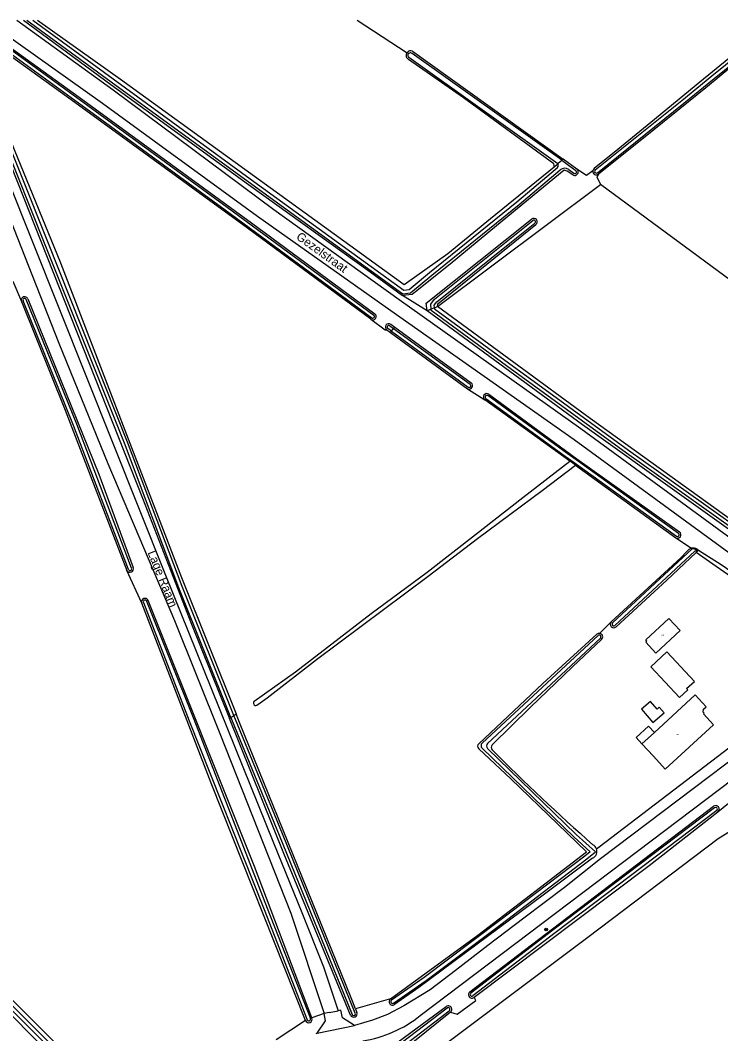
# Model space of a CAD drawing. Extents: x 141000 to 143000, y 400580 to 403500.
# Drawn here: x 142605.5 to 142807.3, y 403208 to 403500 of the extents above; entities that cross this region are included whole.
import ezdxf

# ---------------------------------------------------------------- set-up
doc = ezdxf.new("R2010")
doc.units = 0
for name, color, linetype in [('gg-anno-openbare ruimte label', 7, 'Continuous'), ('gg-bbg-luifel en loopbrug', 7, 'Continuous'), ('gg-bbg-overig bouwwerk', 7, 'Continuous'), ('gg-knt-bronhoudergrens', 7, 'Continuous'), ('gg-knt-onverhard', 7, 'Continuous'), ('gg-knt-verharding', 7, 'Continuous'), ('gg-kntw-bovenkant insteek waterloop', 7, 'Continuous'), ('gg-kntw-waterlijn', 7, 'Continuous'), ('gt-grn-groengrens', 7, 'Continuous'), ('gt-grn-vlakafsluiter', 7, 'Continuous'), ('gt-symb-boom', 7, 'Continuous'), ('gx-grn-maaiveld', 7, 'Continuous'), ('kenmerkpunt-x pandkandidaat', 7, 'Continuous')]:
    doc.layers.add(name, color=color, linetype=linetype)

# ---------------------------------------------------------------- blocks, each defined once
blk = doc.blocks.new('gt0-BOOM')
at = {"layer": 'gt-symb-boom'}
for radius in [0.4, 0.2]:
    blk.add_circle((0, 0), radius, dxfattribs=at)

msp = doc.modelspace()

# ---------------------------------------------------------------- linework, layer by layer
at = {"layer": 'gg-bbg-luifel en loopbrug'}
msp.add_line((142788.18, 403294.8), (142784.59, 403291.5), dxfattribs=at)
msp.add_lwpolyline([(142788.18, 403294.8), (142786.48, 403296.64), (142782.9, 403293.34), (142784.59, 403291.5)], dxfattribs=at)
at = {"layer": 'gg-bbg-overig bouwwerk'}
for points in [[(142797.46, 403307.41), (142799.7, 403309.49), (142791.8, 403318), (142787.17, 403313.7), (142795.37, 403304.87), (142797.76, 403307.09), (142797.46, 403307.41)], [(142789.56, 403302.04), (142788.95, 403301.51), (142787.03, 403303.74), (142784.41, 403301.48), (142787.74, 403297.63), (142790.96, 403300.41), (142789.56, 403302.04)]]:
    msp.add_lwpolyline(points, dxfattribs=at)
at = {"layer": 'gg-knt-bronhoudergrens'}
for p, q in [((142825.88, 403413.4), (142772.65, 403452.66)), ((142640.51, 403332.06), (142636.22, 403341.49)), ((142687.67, 403211.8), (142679.2, 403206.19))]:
    msp.add_line(p, q, dxfattribs=at)
msp.add_lwpolyline([(142724.1, 403202.14), (142744.38, 403217.33), (142769.01, 403235.83), (142806.51, 403264.25), (142811.3, 403267.21), (142815.02, 403266.93), (142818.46, 403266.27), (142827.61, 403256.01), (142851.53, 403228.52), (142860.35, 403218.34), (142869.79, 403206.95)], dxfattribs=at)
at = {"layer": 'gg-knt-onverhard'}
for p, q in [((142725.71, 403417.52), (142772.65, 403452.66)), ((142603.33, 403424.78), (142605.82, 403418.96)), ((142734.29, 403393.84), (142739.3, 403390.63)), ((142794.32, 403350.9), (142798.86, 403347.86)), ((142775.73, 403326.66), (142772.35, 403323.34)), ((142712.14, 403218.02), (142702.06, 403215.16))]:
    msp.add_line(p, q, dxfattribs=at)
msp.add_lwpolyline([(142706.45, 403413.83), (142710.6, 403410.83), (142711.06, 403410.77)], dxfattribs=at)
at = {"layer": 'gg-knt-verharding'}
for p, q in [((142694.45, 403214.07), (142693.01, 403213.78)), ((142694.45, 403214.07), (142697.08, 403214.59)), ((142691, 403208.13), (142701.74, 403210.4))]:
    msp.add_line(p, q, dxfattribs=at)
for points in [[(142580.86, 403500), (142581.54, 403498.3), (142583.38, 403492.84), (142588.51, 403478.21), (142592.66, 403467.56), (142616.56, 403406.94), (142630.76, 403372.28), (142649.91, 403327.04), (142662.96, 403294.46), (142683.41, 403242.72), (142693.01, 403213.78)], [(142585.17, 403500), (142591.93, 403477.83), (142601.39, 403455.15), (142647.31, 403340.12), (142678.4, 403262.94), (142686.61, 403242.88), (142692.87, 403227.3), (142697.08, 403214.59)], [(142595.45, 403500), (142629.17, 403476.1), (142673.83, 403443.54), (142712.26, 403416.36), (142765.07, 403379.18), (142812.16, 403344.83), (142845.71, 403319.06)], [(142604.52, 403500), (142632.22, 403479.92), (142678.54, 403445.48), (142714.62, 403419.55), (142767.02, 403382.42), (142814.6, 403347.5), (142848.6, 403321.46)], [(142720.69, 403213.22), (142849.81, 403310.95), (142851.32, 403311.94)], [(142817.41, 403292.17), (142772.6, 403258.33), (142762.3, 403250.12), (142750.55, 403241.24), (142740.23, 403233.43), (142730.9, 403226.22), (142723.56, 403220.59), (142715.99, 403216.06), (142711.33, 403213.56), (142706.94, 403211.9), (142701.74, 403210.4)], [(142691, 403208.13), (142693.4, 403211.67), (142693.01, 403213.78)], [(142701.74, 403210.4), (142698.3, 403212.61), (142697.85, 403214.74), (142697.08, 403214.59)]]:
    msp.add_lwpolyline(points, dxfattribs=at)
msp.add_arc((142698.62, 403240.77), 35.3, 279.016, 308.6824, dxfattribs=at)
at = {"layer": 'gg-kntw-bovenkant insteek waterloop'}
for p, q in [((142718.48, 403491.13), (142761.89, 403459.95)), ((142765.85, 403457.11), (142761.89, 403459.95)), ((142712.24, 403412.39), (142713.37, 403411.56)), ((142713.37, 403411.56), (142735.38, 403395.51)), ((142711.06, 403410.77), (142712.11, 403410.01)), ((142712.11, 403410.01), (142734.29, 403393.84)), ((142763.85, 403372.96), (142739.3, 403390.63)), ((142765.44, 403371.79), (142794.32, 403350.9)), ((142800.49, 403347.58), (142800.91, 403347.31)), ((142824.75, 403329.45), (142800.19, 403346.65)), ((142735, 403220.05), (142805.23, 403273.51)), ((142702.06, 403215.16), (142702.47, 403214.12))]:
    msp.add_line(p, q, dxfattribs=at)
for points in [[(142589.32, 403500), (142588.32, 403498.23), (142595.87, 403475.4), (142640.71, 403362.28), (142654.81, 403325.96), (142665.77, 403298.81)], [(142591.29, 403500), (142591.97, 403499.88), (142622.44, 403477.83), (142672.13, 403441.68), (142707.63, 403415.45)], [(142606.4, 403500), (142631.57, 403481.47), (142671.28, 403452.65), (142706.32, 403427.52), (142715.57, 403420.68)], [(142610.41, 403500), (142634.4, 403483.03), (142716.07, 403423.83), (142728.67, 403432.77), (142740.99, 403442.9), (142759.27, 403457.81)], [(142706.45, 403413.83), (142670.95, 403440.11), (142621.19, 403476.34), (142591.57, 403497.67), (142591.07, 403497.32), (142597.37, 403478.02), (142617.11, 403430.15), (142651.96, 403339.43), (142667.73, 403300.2)], [(142759.27, 403457.81), (142759.34, 403458.23), (142759.21, 403458.62), (142733.19, 403477.63), (142717.35, 403488.72)], [(142764.66, 403455.5), (142763, 403456.54), (142762.22, 403456.79), (142742.68, 403440.75), (142729.31, 403429.75), (142719.32, 403421.77), (142718.42, 403420.97), (142715.57, 403420.68)], [(142722.71, 403416.24), (142722.41, 403418.46), (142752.79, 403442.7)], [(142725.71, 403417.52), (142725.74, 403418.29), (142754.05, 403441.14)], [(142605.82, 403418.96), (142618.4, 403387.7), (142636.22, 403341.49)], [(142607.68, 403419.72), (142628.11, 403369.24), (142638.04, 403342.31)], [(142893.17, 403355.15), (142861.1, 403330.58), (142853.67, 403324.76), (142852.71, 403324.86), (142818.65, 403349.97), (142769.65, 403385.22), (142725.71, 403417.52)], [(142853.32, 403322.06), (142767.49, 403383.4), (142722.71, 403416.24)], [(142740.48, 403392.24), (142765.8, 403373.67), (142795.43, 403352.56)], [(142672.88, 403303.84), (142684.8, 403312.27), (142706.58, 403329.06), (142722.69, 403341.02), (142736.64, 403351.87), (142750.3, 403362.48), (142763.85, 403372.96)], [(142673.9, 403302.83), (142676.58, 403304.73), (142690.83, 403315.77), (142723.04, 403339.78), (142737.22, 403350.68), (142755.8, 403364.5), (142765.44, 403371.79)], [(142800.91, 403347.31), (142807.38, 403343.19), (142825.51, 403330.74)], [(142775.73, 403326.66), (142795.77, 403345.07), (142797.55, 403346.92)], [(142800.19, 403346.65), (142791.79, 403338.64), (142777.13, 403325.24)], [(142689.53, 403212.53), (142672.99, 403256.21), (142642.37, 403332.79)], [(142687.67, 403211.8), (142660.44, 403280.2), (142640.51, 403332.06)], [(142771.6, 403323.07), (142756.03, 403308.9), (142737.58, 403291.56)], [(142772.96, 403321.61), (142764.55, 403313.73), (142752.47, 403302.06), (142741.43, 403291.2)], [(142700.63, 403213.35), (142681.46, 403259.95), (142665.77, 403298.81)], [(142702.06, 403215.16), (142700.83, 403218.32), (142668.65, 403297.67), (142667.73, 403300.2)], [(142712.14, 403218.02), (142737.33, 403236.4), (142755.32, 403250.18), (142768.64, 403260.4), (142760.31, 403268.39), (142746.84, 403281.38), (142737.56, 403290.08)], [(142640.83, 403175.69), (142632.08, 403184.36), (142617.37, 403198.78), (142602.25, 403214), (142584.13, 403231.28), (142569.16, 403246.61), (142552.14, 403263.78), (142545.24, 403271.12)], [(142547.36, 403273.24), (142563.78, 403256.69), (142581.71, 403239.05), (142615.56, 403205.33), (142633.58, 403187.1), (142640.07, 403180.8), (142642.94, 403177.82)], [(142736.22, 403218.47), (142786.68, 403256.48), (142806.49, 403271.96)], [(142770.32, 403258.54), (142756.54, 403248.17), (142720.32, 403221.27), (142713.31, 403216.4)], [(142706.76, 403199.23), (142707.49, 403200.53), (142728.18, 403215.79)], [(142729.39, 403214.2), (142711.65, 403199.89), (142710.56, 403198.2)]]:
    msp.add_lwpolyline(points, dxfattribs=at)
for centre, radius, start, end in [((142718.01, 403489.88), 1.34, 145.3975, 240.2162), ((142718.01, 403489.88), 1.34, 69.6816, 145.3766), ((142765.25, 403456.3), 1, 233.5938, 53.6059), ((142771.45, 403456.47), 1, 170.6247, 308.752), ((142771.45, 403456.47), 1, 128.8208, 170.5738), ((142753.42, 403441.92), 1, 308.9189, 128.9019), ((142606.75, 403419.34), 1, 22.0612, 202.1162), ((142707.03, 403414.65), 1, 234.5159, 53.6359), ((142711.65, 403411.58), 1, 53.7954, 233.7708), ((142734.78, 403394.71), 1, 240.5064, 53.7852), ((142739.89, 403391.43), 1, 53.901, 233.8715), ((142794.84, 403351.75), 1, 238.0782, 54.4781), ((142799.34, 403345.81), 2.11, 103.1503, 148.2379), ((142799.34, 403345.82), 2.1, 56.8121, 103.1438), ((142637.11, 403341.96), 1, 208.064, 20.8049), ((142641.44, 403332.43), 1, 21.3716, 201.3163), ((142776.45, 403325.97), 1, 136.0569, 312.8487), ((142772.28, 403322.34), 1, 86.2079, 132.896), ((142772.28, 403322.34), 1, 313.023, 86.1965), ((142673.36, 403303.3), 0.723, 131.8106, 319.2005), ((142738.24, 403290.81), 1, 131.9399, 226.7386), ((142742.13, 403290.49), 1, 134.6018, 224.7513), ((143171.97, 403717.68), 607.01, 224.8232, 228.59164), ((142805.83, 403272.71), 1, 311.2184, 127.1306), ((142769.35, 403260.41), 2.3, 22.3736, 60.7484), ((142769.46, 403260.52), 2.16, 293.6218, 20.7352), ((142735.61, 403219.26), 1, 127.5388, 307.5879), ((142712.72, 403217.21), 1, 125.8245, 305.7837), ((142728.79, 403215), 1, 307.3224, 127.3919), ((142701.55, 403213.74), 0.998, 202.6662, 22.653), ((142688.6, 403212.16), 1, 201.3485, 21.3394)]:
    msp.add_arc(centre, radius, start, end, dxfattribs=at)
at = {"layer": 'gg-kntw-waterlijn'}
for p, q in [((142761.52, 403459.65), (142718.36, 403490.42)), ((142760.31, 403458.66), (142717.47, 403489.25)), ((142761.52, 403459.65), (142763.46, 403458.24)), ((142763.46, 403458.24), (142765.55, 403456.7)), ((142763.5, 403456.97), (142764.96, 403455.9)), ((142711.94, 403411.98), (142713.05, 403411.17)), ((142712.42, 403410.39), (142711.35, 403411.18)), ((142712.42, 403410.39), (142734.49, 403394.3)), ((142713.05, 403411.17), (142735.08, 403395.11)), ((142799.09, 403347.66), (142776.11, 403326.34)), ((142776.79, 403325.6), (142799.83, 403346.98)), ((142771.94, 403322.71), (142738.55, 403291.7)), ((142740.1, 403291.63), (142772.62, 403321.98))]:
    msp.add_line(p, q, dxfattribs=at)
for points in [[(142666.15, 403299.08), (142651.19, 403336.44), (142635.5, 403378.1), (142612.5, 403435.81), (142596.66, 403475.31), (142588.83, 403498.25), (142589.71, 403499.59), (142591.74, 403499.5), (142602.77, 403491.6), (142624.99, 403475.45), (142665.07, 403446.19), (142707.33, 403415.05)], [(142607.39, 403500), (142631.69, 403482.29), (142672.19, 403452.77), (142715.71, 403421.17), (142717.94, 403421.43), (142724.03, 403426.56), (142749.19, 403446.9), (142761.02, 403456.89)], [(142609.09, 403500), (142632.28, 403483.1), (142672.78, 403453.58), (142715.98, 403422.21), (142717.52, 403422.39), (142723.39, 403427.34), (142748.55, 403447.67), (142760.25, 403457.54), (142760.43, 403457.91), (142760.45, 403458.32), (142760.31, 403458.66)], [(142666.99, 403299.68), (142652.12, 403336.8), (142636.43, 403378.46), (142613.43, 403436.18), (142597.59, 403475.66), (142589.93, 403498.11), (142590.23, 403498.56), (142591.4, 403498.51), (142602.18, 403490.79), (142624.4, 403474.64), (142664.48, 403445.38), (142706.74, 403414.25)], [(142723.82, 403416.71), (142723.76, 403418.24), (142724.78, 403419.61), (142745.92, 403436.51), (142753.11, 403442.31)], [(142724.81, 403417.13), (142724.77, 403417.92), (142725.51, 403418.9), (142746.55, 403435.73), (142753.73, 403441.53)], [(142636.64, 403341.78), (142620.86, 403383.23), (142606.29, 403419.15)], [(142637.57, 403342.13), (142621.8, 403383.59), (142607.21, 403419.53)], [(142724.81, 403417.13), (142724.84, 403416.9), (142746.18, 403401.27), (142780.76, 403376.1), (142810.98, 403354.58)], [(142810.4, 403353.77), (142780.18, 403375.29), (142745.59, 403400.46), (142723.91, 403416.34), (142723.82, 403416.71)], [(142739.6, 403391.03), (142762.43, 403374.37), (142765.02, 403372.53), (142794.55, 403351.34)], [(142795.14, 403352.15), (142765.6, 403373.34), (142763.01, 403375.18), (142740.19, 403391.84)], [(142765.44, 403371.79), (142764.67, 403372.36), (142763.85, 403372.96)], [(142641.9, 403332.61), (142655.49, 403298.65), (142676.65, 403244.15), (142689.06, 403212.35)], [(142640.97, 403332.25), (142654.13, 403298.11), (142675.71, 403243.79), (142688.13, 403211.98)], [(142666.15, 403299.08), (142666.53, 403298.13), (142680.07, 403265.21), (142701.09, 403213.54)], [(142702.01, 403213.93), (142680.99, 403265.59), (142667.46, 403298.51), (142666.99, 403299.68)], [(142738.53, 403290.25), (142764.96, 403264.71), (142769.65, 403260.43), (142768.13, 403259.18), (142743.3, 403240.29), (142721.8, 403224.17), (142712.43, 403217.62)], [(142713.01, 403216.81), (142722.39, 403223.36), (142743.91, 403239.49), (142768.74, 403258.39), (142771.18, 403260.39), (142765.66, 403265.43), (142740.08, 403290.18)], [(142641.53, 403176.4), (142589.01, 403228.64), (142545.95, 403271.82)], [(142642.24, 403177.11), (142589.72, 403229.35), (142546.65, 403272.53)], [(142805.53, 403273.11), (142758.93, 403237.82), (142735.3, 403219.66)], [(142806.13, 403272.31), (142759.54, 403237.02), (142735.91, 403218.87)], [(142728.48, 403215.39), (142708.78, 403200.36), (142708.23, 403198.83)], [(142709.2, 403198.57), (142709.62, 403199.74), (142729.09, 403214.6)]]:
    msp.add_lwpolyline(points, dxfattribs=at)
for centre, radius, start, end in [((142717.86, 403489.88), 0.737, 47.1437, 238.4762), ((142762.31, 403455.36), 2, 53.5425, 130.2034), ((142765.25, 403456.3), 0.5, 233.5428, 53.5428), ((142771.45, 403456.47), 0.5, 128.7314, 308.7671), ((142753.42, 403441.92), 0.5, 308.9274, 128.8934), ((142606.75, 403419.34), 0.5, 22.0661, 202.0897), ((142707.03, 403414.65), 0.5, 233.647, 53.5989), ((142711.65, 403411.58), 0.5, 53.7369, 233.7616), ((142734.78, 403394.71), 0.5, 233.8317, 53.7345), ((142739.89, 403391.43), 0.5, 53.9219, 233.8969), ((142794.85, 403351.75), 0.5, 234.4887, 54.5692), ((142637.11, 403341.96), 0.5, 200.8647, 20.8647), ((142641.44, 403332.43), 0.5, 21.3633, 201.3454), ((142776.45, 403325.97), 0.5, 132.8423, 312.8615), ((142772.28, 403322.34), 0.5, 313.061, 133.0505), ((142739.23, 403290.97), 1, 132.9871, 225.9856), ((142740.78, 403290.9), 1, 132.7772, 225.8822), ((142805.83, 403272.71), 0.5, 307.1453, 127.1675), ((142735.61, 403219.26), 0.5, 127.5019, 307.5445), ((142712.72, 403217.21), 0.5, 125.7624, 305.8458), ((142701.55, 403213.74), 0.5, 202.6148, 22.7132), ((142728.79, 403215), 0.5, 307.3625, 127.3625), ((142688.6, 403212.16), 0.5, 201.3218, 21.3869)]:
    msp.add_arc(centre, radius, start, end, dxfattribs=at)
at = {"layer": 'gt-grn-groengrens'}
msp.add_line((142702.54, 403500), (142716.91, 403490.64), dxfattribs=at)
at = {"layer": 'gt-grn-vlakafsluiter'}
for p, q in [((142722.71, 403416.24), (142715.57, 403420.68)), ((142724.81, 403417.13), (142723.82, 403416.71)), ((142724.81, 403417.13), (142725.71, 403417.52)), ((142723.82, 403416.71), (142722.71, 403416.24)), ((142713.05, 403411.17), (142713.37, 403411.56)), ((142712.11, 403410.01), (142712.42, 403410.39)), ((142712.42, 403410.39), (142713.05, 403411.17)), ((142800.91, 403347.31), (142800.68, 403347.1)), ((142800.19, 403346.65), (142800.43, 403346.87)), ((142666.15, 403299.08), (142665.77, 403298.81)), ((142666.15, 403299.08), (142666.99, 403299.68)), ((142666.99, 403299.68), (142667.73, 403300.2)), ((142806.49, 403271.96), (142813.1, 403277.34)), ((142693.01, 403213.78), (142689.53, 403212.53))]:
    msp.add_line(p, q, dxfattribs=at)
for points in [[(142761.52, 403459.65), (142761.13, 403459.34), (142760.31, 403458.66)], [(142771.48, 403261.28), (142772.23, 403261.88), (142811.6, 403291.9), (142816.9, 403293.77)], [(142729.39, 403214.2), (142731.38, 403213.66), (142736.75, 403217.55), (142736.22, 403218.47)]]:
    msp.add_lwpolyline(points, dxfattribs=at)
at = {"layer": 'gx-grn-maaiveld'}
for p, q in [((142759.27, 403457.81), (142760.31, 403458.66)), ((142761.89, 403459.95), (142761.52, 403459.65)), ((142800.43, 403346.87), (142800.68, 403347.1))]:
    msp.add_line(p, q, dxfattribs=at)
for points in [[(142771.14, 403456.86), (142796.03, 403476.86), (142804.74, 403483.96), (142816.56, 403493.5), (142819.32, 403495.07), (142821.46, 403494.55), (142834.75, 403485.35), (142845.76, 403500)], [(142817.96, 403495.77), (142801.22, 403482.19), (142787.12, 403470.53), (142777.67, 403462.76), (142770.83, 403457.25)], [(142771.77, 403456.08), (142796.66, 403476.08), (142805.37, 403483.19), (142817.12, 403492.67), (142819.47, 403494), (142821.05, 403493.62), (142834.97, 403483.98)], [(142816.44, 403491.63), (142805.69, 403482.78), (142802.98, 403480.49), (142788.01, 403468.39), (142772.08, 403455.69)], [(142770.46, 403456.63), (142768.61, 403455.28), (142765.85, 403457.11)], [(142772.08, 403455.69), (142771.6, 403454.86), (142772.65, 403452.66)], [(142800.68, 403347.1), (142800.48, 403347.25), (142800.17, 403347.43), (142799.75, 403347.64), (142799.43, 403347.73), (142799.25, 403347.73), (142799.15, 403347.7), (142799.09, 403347.66)], [(142800.43, 403346.87), (142800.25, 403346.98), (142800.09, 403347.03), (142799.96, 403347.03), (142799.83, 403346.98)], [(142785.71, 403321.45), (142792.37, 403327.66), (142795.6, 403324.21), (142788.58, 403317.67), (142785.69, 403320.77), (142786.04, 403321.1), (142785.71, 403321.45)], [(142784.59, 403291.5), (142787.89, 403287.92), (142791.28, 403284.24), (142805.16, 403297.01), (142802.36, 403300.18), (142802.52, 403300.34), (142802.21, 403300.63), (142802.3, 403301.51), (142803.11, 403302.22), (142799.96, 403305.65), (142788.18, 403294.8)]]:
    msp.add_lwpolyline(points, dxfattribs=at)
msp.add_arc((142698.12, 403188.2), 21.17, 109.6443, 110.8185, dxfattribs=at)

# ---------------------------------------------------------------- block references
at = {"layer": 'gt-symb-boom'}
msp.add_blockref('gt0-BOOM', (142757, 403238), dxfattribs=at)

# ---------------------------------------------------------------- texts
at = {"layer": 'gg-anno-openbare ruimte label'}
for s, rotation, p in [('Gezelstraat', 324.2, (142684.77, 403437.14)), ('Lage Raam', 292.1, (142642.12, 403346.61))]:
    msp.add_text(s, height=2.5, rotation=rotation, dxfattribs=at).set_placement(p)
at = {"layer": 'kenmerkpunt-x pandkandidaat'}
for p in [(142790.27, 403322.72), (142794.51, 403294.16)]:
    msp.add_text('PNDK', height=0.2, dxfattribs=at).set_placement(p)

doc.saveas('drawing.dxf')
